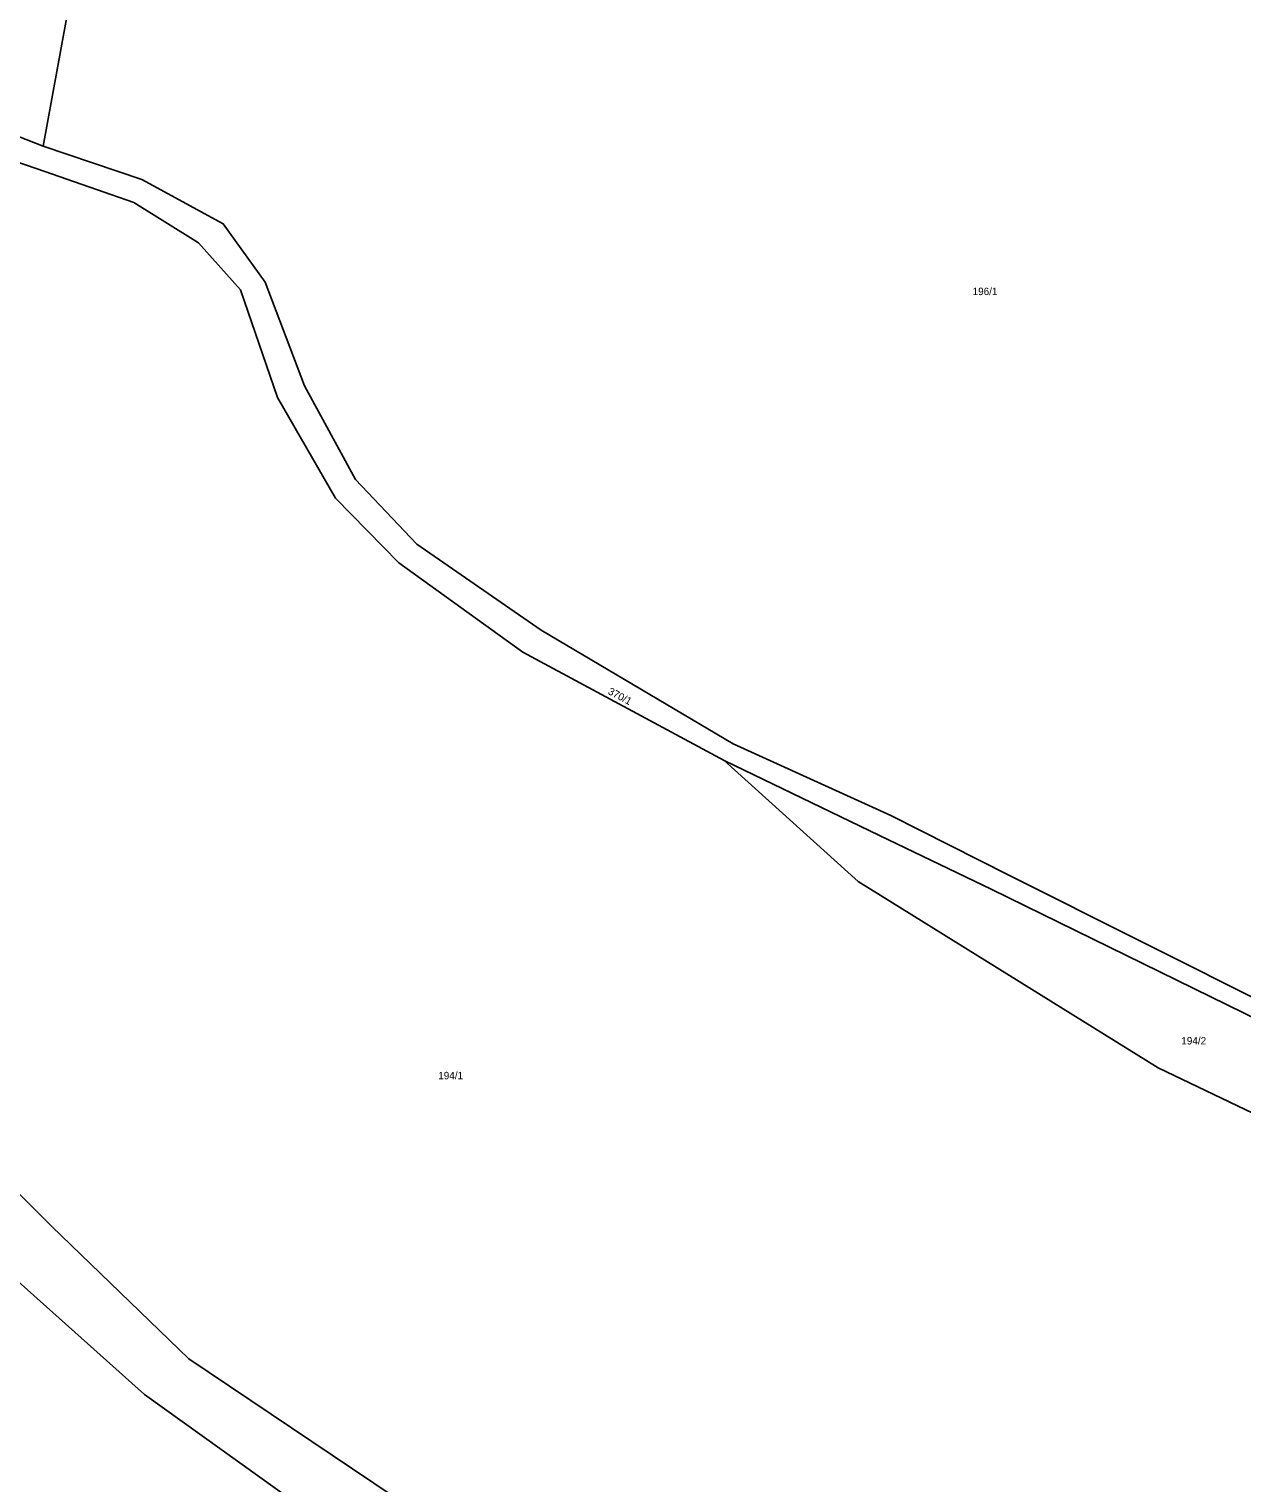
# Model space of a CAD drawing. Extents: x -880531 to -877616, y -1023932 to -1021350.
# Drawn here: x -878177.4 to -877899.3, y -1022969 to -1022635.5 of the extents above; entities that cross this region are included whole.
import ezdxf

# ---------------------------------------------------------------- set-up
doc = ezdxf.new("R2010")
doc.units = 0
doc.layers.add('Hranice parcel', color=7, linetype='Continuous')
doc.layers.add('Parcelní čísla', color=7, linetype='Continuous')

msp = doc.modelspace()

# ---------------------------------------------------------------- linework, layer by layer
at = {"layer": 'Hranice parcel'}
msp.add_line((-878152.5, -1022544.22), (-878174.22, -1022662.33), dxfattribs=at)
for points in [[(-878298.99, -1022642.4), (-878282.71, -1022641.66), (-878239.13, -1022646.52), (-878187.76, -1022657.08), (-878174.22, -1022662.33)], [(-878018.01, -1022803.34), (-878064.23, -1022778.47), (-878092.6, -1022757.94), (-878107.19, -1022743.1), (-878120.43, -1022720.05), (-878128.98, -1022695.35), (-878138.59, -1022684.53), (-878153.41, -1022675.29), (-878175.6, -1022667.53), (-878189.73, -1022662.71), (-878239.29, -1022651.17), (-878283.75, -1022646.37), (-878300.59, -1022646.88)], [(-878174.22, -1022662.33), (-878151.6, -1022670), (-878132.88, -1022680.18), (-878123.3, -1022693.55), (-878114.24, -1022717.33), (-878102.54, -1022738.8), (-878088.47, -1022753.67), (-878059.98, -1022773.42), (-878015.95, -1022799.47), (-877979.79, -1022815.95), (-877952.72, -1022829.64), (-877891.9, -1022860.11), (-877852.43, -1022881.53), (-877842.38, -1022885.55), (-877819.04, -1022889.46), (-877810.95, -1022891.71)], [(-878347.85, -1022769.53), (-878340.08, -1022772.06), (-878314.12, -1022786.74), (-878304.44, -1022794.02), (-878285.98, -1022807.27), (-878250.6, -1022834.52), (-878207.11, -1022875.3), (-878172.27, -1022910.11), (-878140.8, -1022940.6), (-878089.05, -1022975.4), (-878018.43, -1023024.57), (-877994.66, -1023044.33), (-877959.43, -1023078.68), (-877895.65, -1023138.67), (-877846.1, -1023187.34), (-877827.04, -1023210.17), (-877810.32, -1023234.77), (-877793.71, -1023263.48)], [(-877791.31, -1022927.33), (-877805.42, -1022916.68), (-877823.03, -1022907.77), (-877853.57, -1022896.15), (-877894.84, -1022885.1), (-877918.52, -1022873.78), (-877987.3, -1022831.03), (-878018.01, -1022803.34)], [(-877813.48, -1022897.7), (-877819.75, -1022893.8), (-877842.89, -1022889.17), (-877856.11, -1022884.85), (-877894.86, -1022863.21), (-877956.81, -1022832.85), (-877982.39, -1022820.54), (-878018.01, -1022803.34)], [(-877780.67, -1023314.89), (-877785.52, -1023301.59), (-877820.27, -1023240.12), (-877836.64, -1023216.31), (-877856.74, -1023193.96), (-877904.17, -1023147.51), (-877968.01, -1023086.79), (-878004.38, -1023051.82), (-878026.11, -1023034.14), (-878098.6, -1022986.3), (-878150.98, -1022948.79), (-878185.16, -1022918.23), (-878216.86, -1022884.4), (-878262.44, -1022844.37)]]:
    msp.add_lwpolyline(points, dxfattribs=at)

# ---------------------------------------------------------------- texts
at = {"layer": 'Parcelní čísla'}
for s, p in [('196/1', (-877961.04, -1022696.53)), ('194/2', (-877913.18, -1022868.45)), ('194/1', (-878083.59, -1022876.44))]:
    msp.add_text(s, height=1.7, dxfattribs=at).set_placement(p)
msp.add_text('370/1', height=1.7, rotation=332, dxfattribs=at).set_placement((-878044.819, -1022787.96))

doc.saveas('drawing.dxf')
